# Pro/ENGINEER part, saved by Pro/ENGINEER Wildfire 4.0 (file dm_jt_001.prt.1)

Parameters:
  METRIC = "NO"

Other parameters: PITCH, DRILL_DIAMETER, THREAD_DIAMETER, THREADS_PER_INCH, THREAD_DEPTH, THREAD_LENGTH, DRILL_POINT_ANGLE, DRILL_DEPTH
